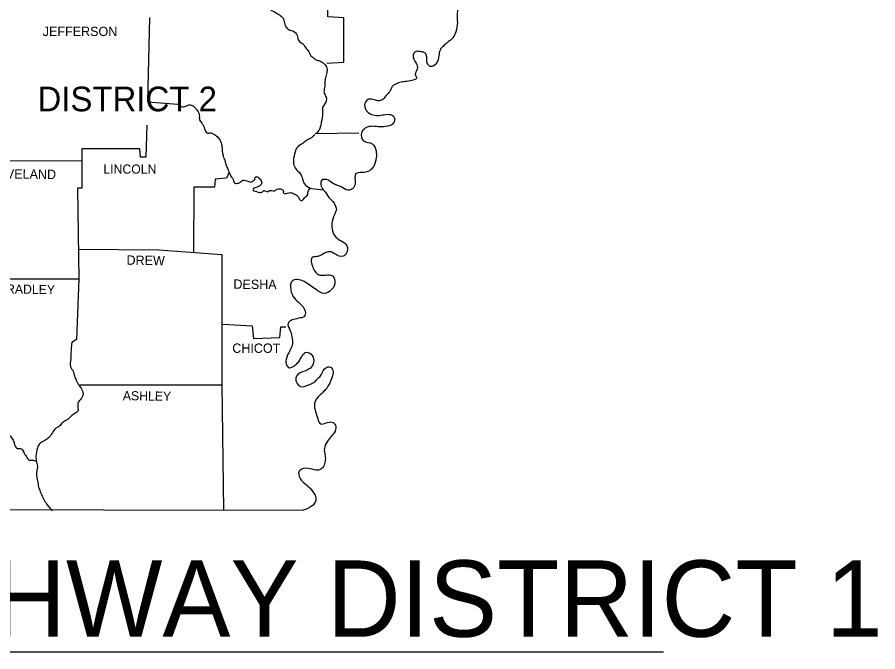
# Model space of a CAD drawing. Extents: x 155 to 3386, y 68 to 2138.
# Drawn here: x 2999.8 to 3385.8, y 1369.4 to 1654.1 of the extents above; entities that cross this region are included whole.
import ezdxf

# ---------------------------------------------------------------- set-up
doc = ezdxf.new("R2010")
doc.units = 0
for name, color, linetype in [('1', 7, 'Continuous'), ('2', 7, 'Continuous'), ('3', 7, 'Continuous')]:
    doc.layers.add(name, color=color, linetype=linetype)

msp = doc.modelspace()

# ---------------------------------------------------------------- linework, layer by layer
at = {"layer": '1'}
msp.add_line((3133.42, 1601.94), (3152.99, 1602.24), dxfattribs=at)
for points in [[(3138.71, 1633.54), (3146.34, 1634.03), (3146.24, 1653.9), (3139.1, 1654.38), (3139.49, 1693.23), (3133.33, 1694.11), (3133.13, 1720.23), (3216.59, 1720.82)], [(3059.06, 1653.99), (3058.28, 1616.13), (3071.88, 1615.05)], [(3057.99, 1605.66), (3057.4, 1591.28), (3055.15, 1591.28), (3054.76, 1595.09), (3028.73, 1595.09), (3028.73, 1589.61)], [(2993.9, 1589.91), (3028.54, 1589.71)], [(3028.73, 1589.71), (3028.83, 1577.48), (3026.78, 1577.38), (3027.36, 1536.78)], [(3094.87, 1584.53), (3093.7, 1581.88), (3088.51, 1581.4), (3088.22, 1577.87), (3078.93, 1577.87), (3078.83, 1548.62)], [(3027.07, 1550.09), (3063.37, 1549.79), (3091.55, 1547.64)], [(3091.55, 1547.64), (3091.55, 1489.13), (3092.33, 1432.87)], [(2983.14, 1536.68), (3027.36, 1536.78)], [(3027.36, 1536.78), (3026.39, 1509.58), (3024.23, 1508.21)], [(3092.04, 1516.43), (3105.15, 1515.65), (3105.73, 1509.97), (3117.57, 1510.36), (3118.06, 1515.16), (3120.31, 1515.16)], [(2769.26, 1512.61), (2769.46, 1433.46), (3128.04, 1432.87)], [(3027.95, 1489.23), (3091.55, 1489.23)]]:
    msp.add_lwpolyline(points, dxfattribs=at)
for points in [[(3210.42, 1697.14), (3208.17, 1694.3), (3204.85, 1696.06), (3204.85, 1698.41), (3205.34, 1700.86), (3204.16, 1702.42), (3202.11, 1701.74), (3202.11, 1698.71), (3201.91, 1695.77), (3201.32, 1691.56), (3202.69, 1690.29), (3205.83, 1689.9), (3208.08, 1689.31), (3209.45, 1687.06), (3209.35, 1684.32), (3208.27, 1681.68), (3206.71, 1679.53), (3204.26, 1678.75), (3202.3, 1680.02), (3201.52, 1682.56), (3200.64, 1684.81), (3198.98, 1686.48), (3197.22, 1684.62), (3196.82, 1681.19), (3196.92, 1678.26), (3196.92, 1674.25), (3199.47, 1671.6), (3201.03, 1668.57), (3200.54, 1665.83), (3198.68, 1662.6), (3197.9, 1659.77), (3197.12, 1655.95), (3197.22, 1651.74), (3196.53, 1647.63), (3195.16, 1644.89), (3192.62, 1642.64), (3190.95, 1641.18), (3189.58, 1639.71), (3188.9, 1636.77), (3188.41, 1634.72), (3186.55, 1632.27), (3185.08, 1632.08), (3183.91, 1633.05), (3183.52, 1634.72), (3183.52, 1636.38), (3182.74, 1638.04), (3180.29, 1638.73), (3178.33, 1638.63), (3177.45, 1637.26), (3178.72, 1633.45), (3179.21, 1631), (3178.53, 1627.67), (3178.92, 1627.28), (3175.4, 1625.42), (3172.56, 1625.13), (3170.21, 1624.44), (3167.96, 1622.98), (3166.88, 1620.82), (3165.32, 1619.06), (3163.95, 1617.4), (3162.09, 1616.62), (3160.04, 1617.01), (3157.3, 1617.3), (3155.73, 1615.35), (3156.22, 1612.51), (3158.08, 1610.85), (3160.82, 1610.06), (3163.66, 1610.26), (3166.4, 1610.55), (3168.94, 1609.18), (3168.45, 1606.54), (3166, 1605.27), (3162.38, 1604.88), (3159.45, 1605.17), (3155.93, 1604.39), (3154.17, 1602.14), (3155.14, 1598.71), (3158.96, 1597.34), (3160.72, 1594.11), (3160.82, 1591.08), (3159.55, 1587.07), (3157.79, 1585.21), (3154.36, 1584.43), (3151.72, 1583.94), (3151.33, 1579.44), (3150.15, 1577.19), (3148.1, 1576.5), (3145.16, 1577.97), (3143.4, 1578.66), (3141.25, 1579.63), (3138.51, 1581.3), (3136.46, 1581), (3137.04, 1576.7), (3137.24, 1576.5), (3139.59, 1573.27), (3141.94, 1570.73), (3143.01, 1567.7)], [(3109.06, 1665.64), (3109.35, 1661.62), (3111.7, 1661.04), (3112.68, 1659.96), (3113.17, 1657.71), (3114.83, 1656.73), (3117.08, 1655.36), (3118.45, 1654.38), (3119.43, 1652.82), (3120.02, 1650.27), (3121.58, 1648.61), (3123.74, 1647.83), (3125.3, 1645.97), (3126.28, 1643.33), (3127.85, 1642.15), (3129.41, 1640.1), (3130.19, 1639.22), (3131.56, 1636.87), (3132.93, 1635.7), (3133.91, 1635.01), (3135.48, 1634.52), (3137.43, 1633.25), (3138.71, 1631.29), (3138.71, 1629.83), (3138.22, 1627.58), (3137.83, 1625.23), (3137.63, 1622.59), (3137.43, 1620.24), (3138.32, 1618.28), (3137.83, 1615.35), (3136.85, 1613.78), (3136.75, 1611.63), (3136.46, 1608.4), (3136.07, 1606.54), (3135.18, 1603.51), (3133.91, 1601.94)], [(3071.88, 1615.05), (3073.35, 1614.07), (3075.4, 1614.17), (3076.77, 1614.76), (3077.85, 1614.66), (3079.32, 1613.78), (3080.3, 1612.61), (3080.98, 1611.73), (3081.47, 1610.36), (3081.47, 1609.08), (3081.96, 1607.32), (3082.55, 1606.64), (3083.33, 1605.37), (3083.82, 1604.19), (3084.11, 1603.41), (3085.19, 1602.14), (3086.17, 1602.24), (3087.05, 1602.14), (3088.22, 1601.45), (3089.98, 1600.08), (3090.28, 1599.69), (3091.45, 1597.15), (3091.65, 1595.58), (3091.84, 1593.53), (3092.23, 1591.57), (3093.02, 1589.42), (3093.41, 1587.95), (3094.29, 1585.9), (3094.87, 1584.53), (3095.66, 1582.76), (3096.83, 1580.81), (3097.32, 1579.63), (3098.98, 1579.73), (3100.16, 1580.22), (3101.04, 1581), (3102.11, 1580.91), (3103.29, 1580.51), (3104.85, 1580.22), (3105.83, 1580.81), (3106.32, 1581.2), (3106.42, 1582.08), (3107.3, 1582.57), (3108.28, 1581.88), (3109.35, 1580.32), (3109.35, 1579.34), (3108.96, 1578.75), (3107.69, 1577.97), (3105.93, 1577.38), (3105.44, 1576.7), (3107.1, 1575.92), (3109.75, 1575.72), (3110.43, 1576.31), (3112.19, 1575.82), (3112.88, 1576.31), (3115.23, 1576.21), (3116.3, 1576.99), (3118.45, 1576.89), (3119.14, 1576.41), (3119.14, 1575.52), (3120.9, 1575.13), (3122.17, 1575.43), (3123.84, 1574.94), (3125.3, 1574.15), (3126.09, 1573.08), (3127.06, 1571.9), (3127.94, 1572.2), (3128.63, 1573.08), (3130.1, 1574.64), (3130.1, 1575.62), (3130.49, 1576.31), (3130.98, 1577.29)], [(3133.23, 1601.35), (3131.17, 1599.69), (3129.41, 1598.71), (3127.55, 1597.34), (3125.3, 1595.68), (3124.23, 1592.84), (3123.64, 1588.93), (3124.42, 1586.58), (3126.18, 1584.53), (3127.36, 1582.86), (3128.24, 1579.93), (3130.39, 1577.87), (3131.08, 1577.58)], [(3143.01, 1567.7), (3142.03, 1565.45), (3140.96, 1561.53), (3141.25, 1558.21), (3142.72, 1555.37), (3145.07, 1553.8), (3147.61, 1551.55), (3147.41, 1548.13), (3145.95, 1546.86), (3142.52, 1547.74), (3139.88, 1548.91), (3137.63, 1548.23), (3134.6, 1546.76), (3132.35, 1546.47), (3132.45, 1541.77), (3135.48, 1538.44), (3138.12, 1538.44), (3141.15, 1538.05), (3142.23, 1534.53), (3140.47, 1531.59), (3137.53, 1530.13), (3133.81, 1531.89), (3131.17, 1533.75), (3128.53, 1535.51), (3125.2, 1536.39), (3123.35, 1536), (3122.47, 1531.89), (3124.03, 1528.17), (3126.57, 1525.63), (3128.92, 1522.3), (3128.53, 1519.85), (3126.77, 1519.17), (3123.64, 1518.48), (3121.78, 1517.51), (3121.29, 1516.72), (3122.27, 1513.4), (3123.15, 1509.78), (3123.15, 1507.04), (3122.07, 1504.49), (3120.41, 1500.58), (3120.61, 1498.03), (3121.78, 1496.86), (3123.25, 1497.25), (3125.2, 1498.62), (3126.48, 1500.19), (3127.55, 1502.14), (3129.61, 1503.81), (3132.15, 1502.34), (3132.74, 1499.31), (3131.27, 1496.67), (3129.22, 1495.49), (3126.67, 1494.51), (3124.81, 1492.36), (3125.3, 1489.82), (3126.77, 1488.45), (3130.39, 1489.13), (3132.84, 1490.21), (3134.21, 1491.58), (3135.87, 1493.24), (3136.75, 1494.9), (3138.02, 1496.67), (3140.27, 1497.15), (3141.35, 1495.69), (3140.96, 1492.36), (3139.59, 1489.23), (3137.73, 1486.59), (3135.67, 1484.73), (3133.13, 1480.72), (3133.62, 1477), (3134.6, 1473.97), (3135.97, 1471.62), (3138.32, 1472.11), (3140.96, 1472.4), (3142.52, 1471.13), (3142.33, 1468.39), (3140.37, 1465.75), (3138.51, 1463.2), (3137.53, 1459.68), (3137.92, 1457.24), (3137.92, 1454.98), (3137.14, 1452.54), (3135.77, 1451.17), (3132.15, 1451.27), (3128.34, 1451.66), (3126.28, 1450.48), (3126.67, 1447.16), (3128.92, 1444.71), (3130.49, 1443.44), (3132.74, 1440.7), (3133.72, 1438.45), (3133.42, 1436.49), (3132.05, 1434.83), (3128.04, 1432.87)], [(3024.23, 1508.21), (3023.94, 1505.18), (3023.84, 1502.34), (3023.65, 1499.6), (3023.65, 1497.55), (3024.82, 1495.3), (3025.51, 1493.14), (3026.19, 1491.28), (3027.56, 1488.84), (3028.83, 1486.98), (3029.22, 1484.34), (3028.44, 1482.97), (3026.97, 1480.91), (3026.87, 1477.19), (3025.11, 1476.02), (3022.86, 1474.06), (3021.59, 1473.18), (3020.22, 1472.3), (3018.75, 1470.74), (3016.6, 1469.27), (3015.04, 1466.82), (3013.28, 1464.96), (3011.81, 1463.99), (3009.75, 1462.71), (3008.87, 1460.76), (3008.19, 1457.14), (3008.48, 1454.5), (3008.87, 1452.15), (3008.38, 1449.21), (3008.87, 1445.98), (3009.36, 1443.44), (3010.14, 1441.19), (3011.22, 1438.65), (3012.59, 1436.3), (3015.53, 1432.68)], [(2926.69, 1485.61), (2928.25, 1486.69), (2929.72, 1487.27), (2931.19, 1486.98), (2932.75, 1486.78), (2934.12, 1486.98), (2935.88, 1486.69), (2937.35, 1485.8), (2939.01, 1485.12), (2940.68, 1485.12), (2942.14, 1485.12), (2943.42, 1484.24), (2945.77, 1484.34), (2947.72, 1485.12), (2949.68, 1485.71), (2952.32, 1486), (2954.67, 1484.34), (2956.33, 1482.97), (2957.7, 1481.4), (2958.68, 1479.64), (2959.76, 1478.66), (2961.52, 1477.98), (2962.89, 1477.68), (2964.55, 1477.19), (2965.43, 1476.8), (2966.21, 1474.94), (2967.49, 1472.4), (2969.93, 1471.52), (2972.96, 1472.69), (2975.41, 1473.38), (2977.17, 1473.97), (2978.25, 1474.36), (2979.23, 1474.46), (2978.93, 1474.65), (2980.11, 1474.94), (2981.18, 1474.16), (2981.87, 1473.09), (2983.04, 1471.52), (2984.12, 1470.15), (2985.19, 1469.66), (2986.27, 1470.25), (2987.74, 1469.76), (2989.01, 1469.27), (2990.48, 1468.88), (2991.75, 1468.78), (2993.41, 1468.39), (2994.69, 1467.7), (2995.86, 1467.02), (2997.03, 1465.75), (2998.21, 1463.79), (2998.6, 1462.23), (2999.97, 1460.66), (3001.24, 1460.66), (3003.1, 1458.12), (3003.78, 1457.14), (3005.25, 1455.38), (3006.33, 1455.38), (3008.38, 1454.98)]]:
    msp.add_spline(points, degree=3, dxfattribs=at)
at = {"layer": '2'}
msp.add_line((2625.16, 1369.37), (3289.7, 1369.37), dxfattribs=at)
at = {"layer": '3'}
msp.add_line((3130.78, 1577.48), (3136.95, 1576.7), dxfattribs=at)

# ---------------------------------------------------------------- texts
at = {"layer": '2'}
for s, height, p in [('JEFFERSON', 4.207, (3011.22, 1645.68)), ('LINCOLN', 4.109, (3038.42, 1583.94)), ('CHICOT', 4.207, (3096.24, 1503.51)), ('ARKANSAS HIGHWAY DISTRICT 1', 34.244, (2645.08, 1376.13))]:
    msp.add_text(s, height=height, dxfattribs=at).set_placement(p)
for s, height, rotation, p in [('CLEVELAND', 4.207, 359.3377, (2983.73, 1581.88)), ('DREW', 4.206, 359.2258, (3048.79, 1543.04)), ('DESHA', 4.206, 359.3704, (3096.73, 1532.28)), ('BRADLEY', 4.108, 359.1449, (2991.07, 1530.22)), ('ASHLEY', 4.109, 359.2361, (3047.13, 1482.28))]:
    msp.add_text(s, height=height, rotation=rotation, dxfattribs=at).set_placement(p)
at = {"layer": '3'}
msp.add_text('DISTRICT 2', height=11.056, dxfattribs=at).set_placement((3008.87, 1611.92))

doc.saveas('drawing.dxf')
